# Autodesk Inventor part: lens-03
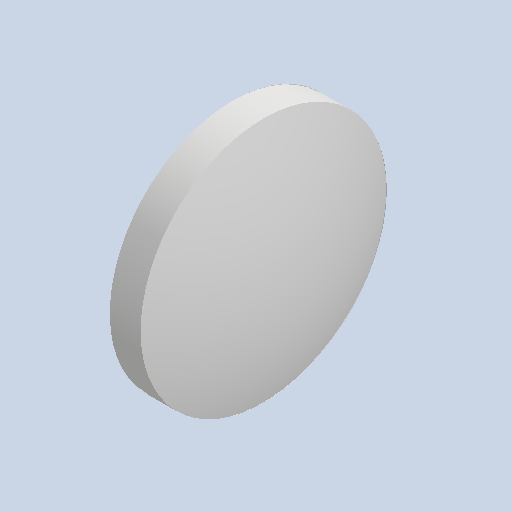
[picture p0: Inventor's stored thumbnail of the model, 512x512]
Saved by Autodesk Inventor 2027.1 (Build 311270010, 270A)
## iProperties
Created: 2026-07
Part Number: lens-03
Material: Generic
Document SubType Name: Modeling
Designer: dunge
Density: 1 g/cm^3
Appearance: Default
Author: dunge
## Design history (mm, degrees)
derived "lens.ipt"
feature "Lens::lens.ipt"
tag "TaggingFeature1"
node "Finishes"
node "Lens"
node "Finish1" dims "Finish1_Area" = 334.42694
other parameters: "SIDE_2_MINOR" = 1.27, "LENS_RADIUS" = 20.32, "SIDE_1_MINOR" = 3.81, "SIDE_1_MAJOR" = 8.89, "SIDE_2_MAJOR" = 3.81
